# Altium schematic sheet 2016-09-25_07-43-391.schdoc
size 453 x 220 mm; SheetNumber: 1; SheetTotal: 1
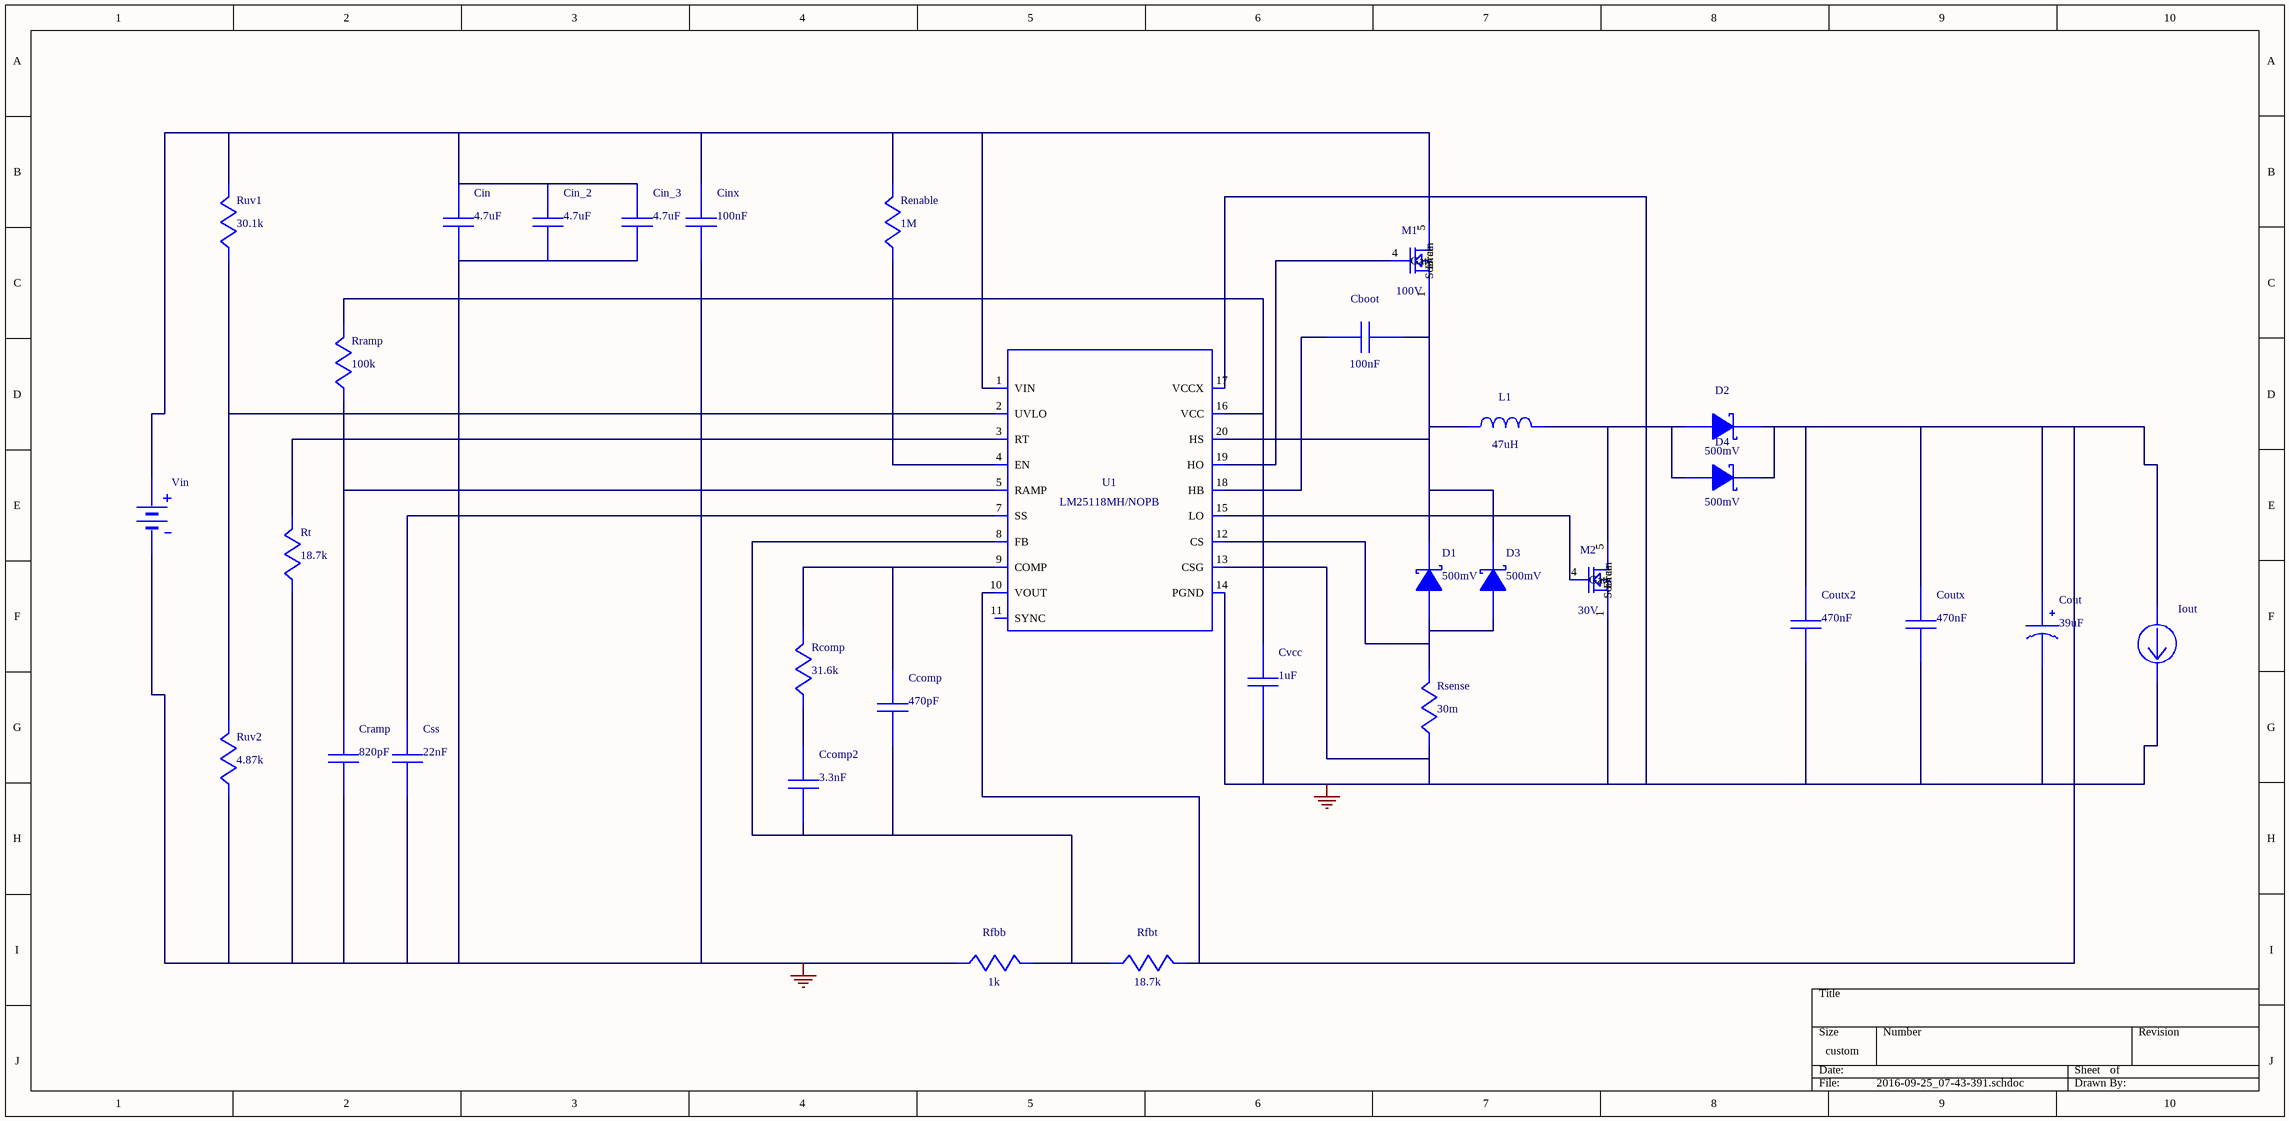
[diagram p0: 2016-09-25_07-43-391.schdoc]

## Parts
Cboot  value 100nF  (hidden comment: GRM21BR71E104KA01L)
Ccomp  value 470pF  (hidden comment: CC0805KRX7R9BB471)
Ccomp2  value 3.3nF  (hidden comment: GRM216R71E332KA01D)
Cin  value 4.7uF  (hidden comment: GRM31CR71H475KA12L)
Cin_2  value 4.7uF  (hidden comment: GRM31CR71H475KA12L)
Cin_3  value 4.7uF  (hidden comment: GRM31CR71H475KA12L)
Cinx  value 100nF  (hidden comment: C0805C104K5RACTU)
Cout  value 39uF  (hidden comment: 35SVPF39M)
Coutx  value 470nF  (hidden comment: C3216JB2A474K)
Coutx2  value 470nF  (hidden comment: C3216JB2A474K)
Cramp  value 820pF  (hidden comment: CC0805KRX7R9BB821)
Css  value 22nF  (hidden comment: CC0805KRX7R9BB223)
Cvcc  value 1uF  (hidden comment: EMK212B7105KG-T)
D1  value 500mV  (hidden comment: B340A-13-F)
D2  value 500mV  (hidden comment: B340A-13-F)
D3  value 500mV  (hidden comment: B340A-13-F)
D4  value 500mV  (hidden comment: B340A-13-F)
Iout  WB_CURRENT_LOAD  (value not drawn)
L1  value 47uH  (hidden comment: MSS1210-473MEB)
M1  value 100V  (hidden comment: CSD19537Q3)
M2  value 30V  (hidden comment: CSD17308Q3)
Rcomp  value 31.6k  (hidden comment: CRCW040231K6FKED)
Renable  value 1M  (hidden comment: CRCW04021M00FKED)
Rfbb  value 1k  (hidden comment: CRCW04021K00FKED)
Rfbt  value 18.7k  (hidden comment: CRCW040218K7FKED)
Rramp  value 100k  (hidden comment: CRCW0402100KFKED)
Rsense  value 30m  (hidden comment: CSR1206FK30L0)
Rt  value 18.7k  (hidden comment: CRCW040218K7FKED)
Ruv1  value 30.1k  (hidden comment: CRCW040230K1FKED)
Ruv2  value 4.87k  (hidden comment: CRCW04024K87FKED)
U1  LM25118MH/NOPB
Vin  WB_BATTERY  (value not drawn)

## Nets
0: Cin.2 Cin_2.2 Cin_3.2 Cinx.2 Cout.2(-) Coutx.2 Coutx2.2 Cramp.2 Css.2 Cvcc.2 Iout.2(-) M2.1(Source) M2.2(Source) M2.3(Source) Rfbb.2 Rsense.2 Rt.2 Ruv2.2 U1.6(AGND) U1.13(CSG) U1.14(PGND) U1.17(VCCX) U1.21(EXP-PAD) Vin.2(-)
NetCboot_1: Cboot.1 D1.1(K) D3.1(K) L1.2 M1.1(Source) M1.2(Source) M1.3(Source) U1.20(HS)
NetCboot_2: Cboot.2 U1.18(HB)
NetCcomp2_1: Ccomp2.1 Rcomp.2
NetCcomp_1: Ccomp.1 Rcomp.1 U1.9(COMP)
NetCcomp_2: Ccomp.2 Ccomp2.2 Rfbb.1 Rfbt.2 U1.8(FB)
NetCin_1: Cin.1 Cin_2.1 Cin_3.1 Cinx.1 M1.5(Drain) M1.6(Drain) M1.7(Drain) M1.8(Drain) M1.9(Drain) Renable.1 Ruv1.1 U1.1(VIN) Vin.1(+)
NetCout_1: Cout.1(+) Coutx.1 Coutx2.1 D2.1(K) D4.1(K) Iout.1(+) Rfbt.1 U1.10(VOUT)
NetCramp_1: Cramp.1 Rramp.2 U1.5(RAMP)
NetCss_1: Css.1 U1.7(SS)
NetCvcc_1: Cvcc.1 Rramp.1 U1.16(VCC)
NetD1_2: D1.2(A) D3.2(A) Rsense.1 U1.12(CS)
NetD2_2: D2.2(A) D4.2(A) L1.1 M2.5(Drain) M2.6(Drain) M2.7(Drain) M2.8(Drain) M2.9(Drain)
NetM1_4: M1.4(Gate) U1.19(HO)
NetM2_4: M2.4(Gate) U1.15(LO)
NetRenable_2: Renable.2 U1.4(EN)
NetRt_1: Rt.1 U1.3(RT)
NetRuv1_2: Ruv1.2 Ruv2.1 U1.2(UVLO)

Not connected (* = marked no-connect by the designer): U1 11(SYNC)

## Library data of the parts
Cboot = GRM21BR71E104KA01L: GRM21BR71E104KA0; Manufacturer Name: MuRata
Ccomp = CC0805KRX7R9BB471: CC0805KRX7R9BB47; Manufacturer Name: Yageo America
Ccomp2 = GRM216R71E332KA01D: GRM216R71E332KA0; Manufacturer Name: MuRata
Cin Cin_2 Cin_3 = GRM31CR71H475KA12L: GRM31CR71H475KA1; Manufacturer Name: MuRata
Cinx = C0805C104K5RACTU: Manufacturer Name: Kemet
Cout = 35SVPF39M: Manufacturer Name: Panasonic
Coutx Coutx2 = C3216JB2A474K: Manufacturer Name: TDK
Cramp = CC0805KRX7R9BB821: CC0805KRX7R9BB82; Manufacturer Name: Yageo America
Css = CC0805KRX7R9BB223: CC0805KRX7R9BB22; Manufacturer Name: Yageo America
Cvcc = EMK212B7105KG-T: Manufacturer Name: Taiyo Yuden
D1-D4 = B340A-13-F: Manufacturer Name: Diodes Inc.
L1 = MSS1210-473MEB: Unknown; Manufacturer Name: Coilcraft
M1 = CSD19537Q3: Manufacturer Name: Texas Instruments
M2 = CSD17308Q3: Manufacturer Name: Texas Instruments
Rcomp = CRCW040231K6FKED: Manufacturer Name: Vishay-Dale
Renable = CRCW04021M00FKED: Manufacturer Name: Vishay-Dale
Rfbb = CRCW04021K00FKED: Manufacturer Name: Vishay-Dale
Rfbt Rt = CRCW040218K7FKED: Manufacturer Name: Vishay-Dale
Rramp = CRCW0402100KFKED: Manufacturer Name: Vishay-Dale
Rsense = CSR1206FK30L0: Manufacturer Name: Stackpole Electronics Inc
Ruv1 = CRCW040230K1FKED: Manufacturer Name: Vishay-Dale
Ruv2 = CRCW04024K87FKED: Manufacturer Name: Vishay-Dale
U1 = LM25118MH/NOPB: Manufacturer Name: Texas Instruments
